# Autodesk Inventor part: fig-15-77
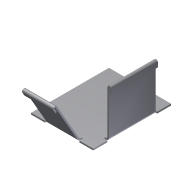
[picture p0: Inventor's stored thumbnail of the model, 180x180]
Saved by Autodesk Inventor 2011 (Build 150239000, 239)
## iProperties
Shininess: 77.0
Angle Display Precision: 2
Document Length Units: 11269
Document Angle Units: 11279
Document Time Units: 11290
Document Mass Units: 11283
Document Length Units Precision: 3
Document Angle Units Precision: 2
Compacted: True
Created: 2002-04
Part Number: fig-15-77
Document SubType Name: Sheet Metal
Density: 1 g/cm^3
Sheet Metal Rule: Default
Density: 0.0
Volumn: 0.0
Area: 0.0
PropertySet Name: Model Information
Control State: 0
Master: False
Checked Out: False
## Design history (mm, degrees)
node "Face1"
  sketch "Sketch1"
    geometry: L1 (-17.882, 11.882)-(2.118, 11.882); L2 (2.118, 11.882)-(2.118, -13.176); L3 (2.118, -13.176)-(-17.882, -13.176); L4 (-17.882, -13.176)-(-17.882, 11.882)
    constraints: 8 end point, 2 parallel, 1 horizontal, 1 perpendicular
    dimensions: "d17" = 20 distance of L2.end L3.end
node "Flange2"
node "Flange3"
feature "Hem8" dims "d82" = 0.5 (= BendReliefWidth), "d83" = 0.25 (= BendReliefDepth), "d84" = 1 (= MinimumRemnant), "d85" = 0.5 (= BendRadius), "d86" = 2 (= 4 x Thickness), "d87" = 0.25 (= 0.5 x Thickness), "d88" = 0.125 (= 0.5 x d87), "SeamGap" = 0.01, "Thickness" = 0.5
feature "Hem9" dims "d89" = 0.5 (= BendReliefWidth), "d90" = 0.25 (= BendReliefDepth), "d91" = 1 (= MinimumRemnant), "d92" = 0.5 (= BendRadius), "d93" = 2 (= 4 x Thickness), "d94" = 0.25 (= 0.5 x Thickness), "d95" = 0.125 (= 0.5 x d94), "SeamGap" = 0.01, "Thickness" = 0.5
body "Solid1"
face "Plate1" dims "Thickness" = 0.5
sketch "Sketch3"
  geometry: L1 (5, 0)-(20, 0); L2 (20, 0)-(20, 15); L3 (20, 15)-(5, 15); L4 (5, 15)-(5, 0)
  constraints: 8 end point
face "Plate3" dims "d6" = 15, "d7" = 90 deg, "d8" = 0.5 (= BendRadius), "d18" = 5, "d19" = 15, "Thickness" = 0.5, "MinimumRemnant" = 1 (= 2 x Thickness), "BendReliefWidth" = 0.5 (= Thickness)
bend "Bend2" dims "d6" = 15, "d7" = 90 deg, "d8" = 0.5 (= BendRadius), "d56" = 0.5 (= BendReliefWidth), "d57" = 0.25 (= BendReliefDepth), "d58" = 1 (= MinimumRemnant), "SeamGap" = 0.01, "Thickness" = 0.5, "MinimumRemnant" = 1 (= 2 x Thickness), "BendReliefWidth" = 0.5 (= Thickness), "TransitionRadius" = 0.5 (= BendRadius)
sketch "Sketch6"
  geometry: L1 (15, 0)-(5, 0); L2 (5, 0)-(5, 15); L3 (5, 15)-(15, 15); L4 (15, 15)-(15, 0)
  constraints: 8 end point
face "Plate4" dims "d20" = 5, "d21" = 10, "d23" = 15, "d24" = 60 deg, "d25" = 0.5 (= BendRadius), "Thickness" = 0.5, "MinimumRemnant" = 1 (= 2 x Thickness), "BendReliefWidth" = 0.5 (= Thickness)
bend "Bend3" dims "d22" = 0.5 (= BendRadius), "d23" = 15, "d24" = 60 deg, "d25" = 0.5 (= BendRadius), "d59" = 0.5 (= BendReliefWidth), "d60" = 0.25 (= BendReliefDepth), "d61" = 1 (= MinimumRemnant), "SeamGap" = 0.01, "Thickness" = 0.5, "MinimumRemnant" = 1 (= 2 x Thickness), "BendReliefWidth" = 0.5 (= Thickness)
sketch "Sketch12"
  geometry: L1 (0.433, 0.25)-(0, 0); L2 (-0.217, -0.125)-(0.471, -1.316); L3 (0.471, -1.316)-(0.038, -1.566); L4 (0.038, -1.566)-(-0.65, -0.375); A1 r 0.125 centre (-0.108, -0.063) between (0, 0) and (-0.217, -0.125); A2 r 0.625 centre (-0.108, -0.063) between (0.433, 0.25) and (-0.65, -0.375)
  constraints: 8 end point, 4 point on circle
sketch "Sketch13"
  geometry: L1 (0.5, 0)-(0, 0); L2 (-0.25, 0)-(-0.25, -1.375); L3 (-0.25, -1.375)-(-0.75, -1.375); L4 (-0.75, -1.375)-(-0.75, 0); A1 r 0.125 centre (-0.125, 0) between (0, 0) and (-0.25, 0); A2 r 0.625 centre (-0.125, 0) between (0.5, 0) and (-0.75, 0)
  constraints: 8 end point, 4 point on circle
other parameters: "BendRadius" = 0.5 (= Thickness), "BendReliefDepth" = 0.25 (= 0.5 x Thickness), "CornerReliefSize" = 2 (= 4 x Thickness), "d0" = 0.5 (= BendRadius), "d5" = 0.5 (= BendRadius), "d26" = 0.5 (= BendRadius), "d30" = 0.5 (= BendRadius), "JacobiRadiusSize" = 0.5 (= Thickness), "GapSize" = 0.5 (= Thickness)
